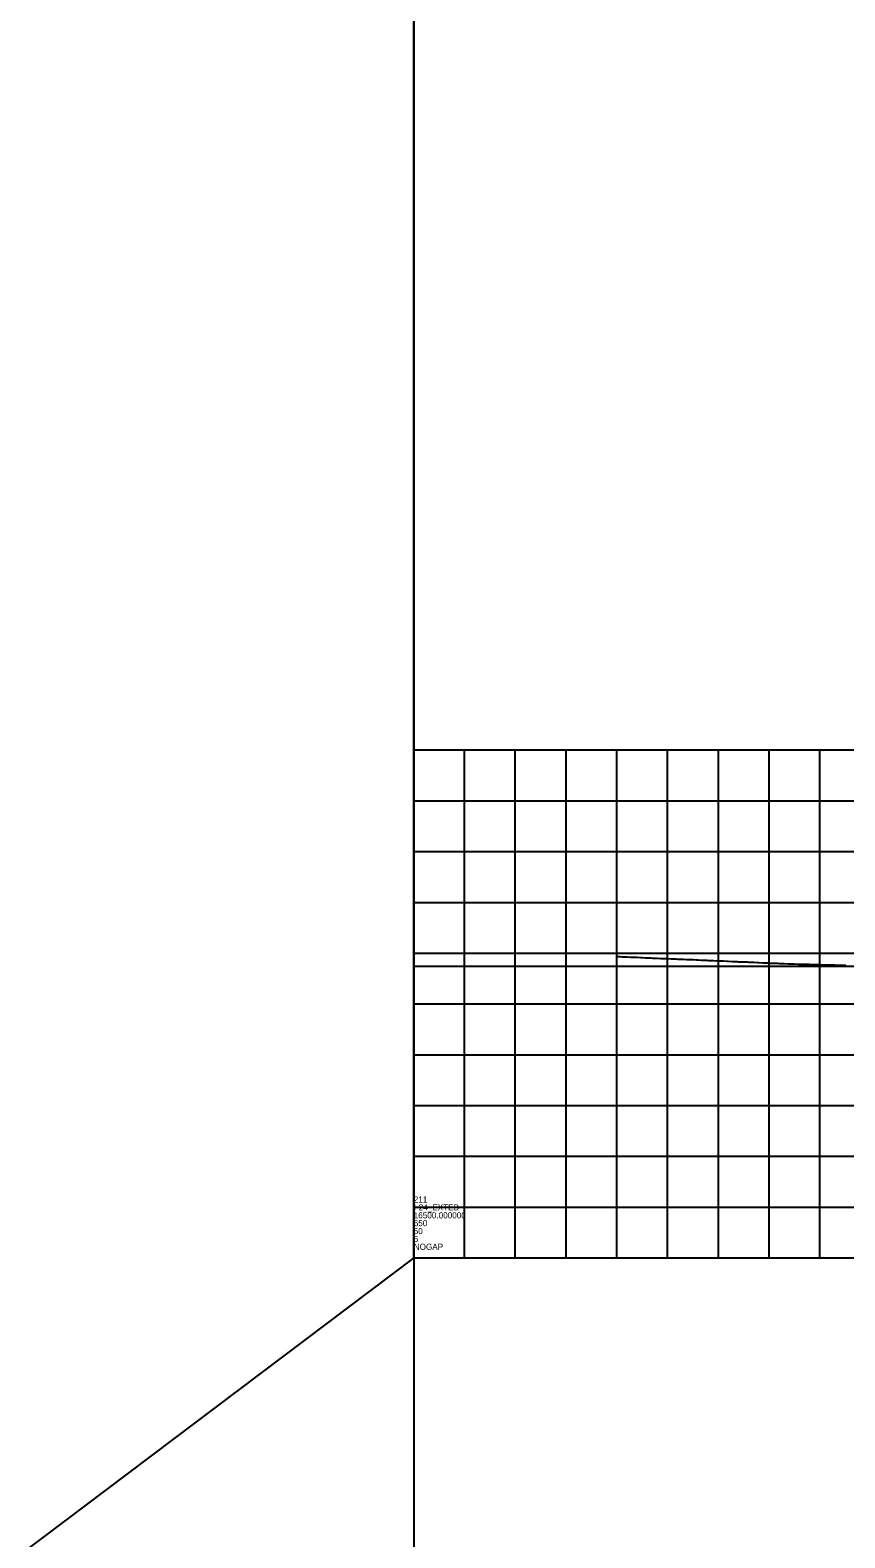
# Model space of a CAD drawing. Extents: x -7164 to 2214450, y -19642 to 253469.
# Drawn here: x -378 to 425, y -12276 to -10791 of the extents above; entities that cross this region are included whole.
import ezdxf

# ---------------------------------------------------------------- set-up
doc = ezdxf.new("R2010")
doc.units = 0
for name, color, linetype in [('DESIGN - SCRATCH - User 1', 7, 'Continuous'), ('DESIGN - SHEET - Light Grid', 7, 'Continuous'), ('SURVEY - PROFILE - Ground Line with Text', 7, 'Continuous'), ('XTREE', 7, 'Continuous')]:
    doc.layers.add(name, color=color, linetype=linetype)

msp = doc.modelspace()

# ---------------------------------------------------------------- linework, layer by layer
at = {"layer": 'DESIGN - SCRATCH - User 1'}
for p, q in [((1500, -11500), (0, -11500)), ((0, -11500), (0, -12000)), ((1500, -11500), (0, -11500)), ((0, -11500), (0, -12000)), ((0, -12000), (-6163.5, -16642.5)), ((0, -12000), (-6163.5, -16642.5)), ((0, -12000), (1500, -12000)), ((0, -12000), (1500, -12000))]:
    msp.add_line(p, q, dxfattribs=at)
at = {"layer": 'DESIGN - SHEET - Light Grid'}
for p, q in [((0, -9000), (0, -11500)), ((0, -9000), (0, -11500)), ((0, -12000), (0, -9500)), ((0, -12000), (0, -9500)), ((50, -12000), (50, -11500)), ((50, -12000), (50, -11500)), ((100, -12000), (100, -11500)), ((100, -12000), (100, -11500)), ((150, -12000), (150, -11500)), ((150, -12000), (150, -11500)), ((200, -12000), (200, -11500)), ((200, -12000), (200, -11500)), ((250, -12000), (250, -11500)), ((250, -12000), (250, -11500)), ((300, -12000), (300, -11500)), ((300, -12000), (300, -11500)), ((350, -12000), (350, -11500)), ((350, -12000), (350, -11500)), ((400, -12000), (400, -11500)), ((400, -12000), (400, -11500)), ((0, -11550), (1500, -11550)), ((0, -11550), (1500, -11550)), ((0, -11600), (1500, -11600)), ((0, -11600), (1500, -11600)), ((0, -11650), (1500, -11650)), ((0, -11650), (1500, -11650)), ((0, -11700), (1500, -11700)), ((0, -11700), (1500, -11700)), ((0, -11750), (1500, -11750)), ((0, -11750), (1500, -11750)), ((0, -11800), (1500, -11800)), ((0, -11800), (1500, -11800)), ((0, -11850), (1500, -11850)), ((0, -11850), (1500, -11850)), ((0, -11900), (1500, -11900)), ((0, -11900), (1500, -11900)), ((0, -11950), (1500, -11950)), ((0, -11950), (1500, -11950)), ((0, -12000), (1400, -12000)), ((0, -12000), (0, -14500)), ((0, -12000), (1400, -12000)), ((0, -12000), (0, -14500))]:
    msp.add_line(p, q, dxfattribs=at)
at = {"layer": 'SURVEY - PROFILE - Ground Line with Text'}
msp.add_lwpolyline([(200, -11703.2), (200.3, -11703.3), (203.4, -11703.4), (205.3, -11703.5), (208.4, -11703.6), (210.3, -11703.7), (213.4, -11703.8), (215.3, -11703.9), (218.4, -11704), (220.3, -11704.1), (223.4, -11704.2), (225.3, -11704.3), (228.4, -11704.5), (230.2, -11704.5), (233.4, -11704.7), (235.2, -11704.8), (238.4, -11704.9), (240.2, -11705), (243.5, -11705.1), (245.2, -11705.2), (248.5, -11705.3), (250.2, -11705.4), (253.5, -11705.5), (255.2, -11705.6), (258.5, -11705.7), (260.2, -11705.8), (263.5, -11705.9), (265.2, -11706), (268.5, -11706.1), (270.1, -11706.2), (273.5, -11706.4), (275.1, -11706.4), (278.5, -11706.6), (280.1, -11706.7), (283.5, -11706.8), (285.1, -11706.9), (288.6, -11707), (290.1, -11707.1), (293.6, -11707.2), (295.1, -11707.3), (298.6, -11707.4), (300.1, -11707.5), (303.6, -11707.7), (305.1, -11707.7), (308.6, -11707.9), (310, -11707.9), (313.6, -11708.1), (315, -11708.2), (318.6, -11708.3), (320, -11708.4), (323.6, -11708.5), (325, -11708.6), (328.6, -11708.7), (330, -11708.8), (333.7, -11709), (335, -11709), (338.7, -11709.2), (339.9, -11709.2), (343.7, -11709.4), (344.9, -11709.4), (348.7, -11709.6), (349.9, -11709.7), (353.7, -11709.8), (354.9, -11709.9), (358.7, -11710), (359.9, -11710.1), (363.7, -11710.2), (364.9, -11710.3), (368.7, -11710.4), (369.9, -11710.4), (373.8, -11710.6), (374.9, -11710.6), (378.8, -11710.7), (379.8, -11710.8), (383.8, -11710.9), (384.8, -11710.9), (388.8, -11711), (389.8, -11711), (393.8, -11711.1), (394.8, -11711.1), (398.8, -11711.2), (399.8, -11711.3), (403.8, -11711.4), (404.8, -11711.4), (408.8, -11711.5), (409.8, -11711.5), (413.8, -11711.6), (414.7, -11711.6), (418.9, -11711.7), (419.7, -11711.8), (421.4, -11711.8), (425.6, -11711.9)], dxfattribs=at)
msp.add_lwpolyline([(200, -11703.2), (200.3, -11703.3), (203.4, -11703.4), (205.3, -11703.5), (208.4, -11703.6), (210.3, -11703.7), (213.4, -11703.8), (215.3, -11703.9), (218.4, -11704), (220.3, -11704.1), (223.4, -11704.2), (225.3, -11704.3), (228.4, -11704.5), (230.2, -11704.5), (233.4, -11704.7), (235.2, -11704.8), (238.4, -11704.9), (240.2, -11705), (243.5, -11705.1), (245.2, -11705.2), (248.5, -11705.3), (250.2, -11705.4), (253.5, -11705.5), (255.2, -11705.6), (258.5, -11705.7), (260.2, -11705.8), (263.5, -11705.9), (265.2, -11706), (268.5, -11706.1), (270.1, -11706.2), (273.5, -11706.4), (275.1, -11706.4), (278.5, -11706.6), (280.1, -11706.7), (283.5, -11706.8), (285.1, -11706.9), (288.6, -11707), (290.1, -11707.1), (293.6, -11707.2), (295.1, -11707.3), (298.6, -11707.4), (300.1, -11707.5), (303.6, -11707.7), (305.1, -11707.7), (308.6, -11707.9), (310, -11707.9), (313.6, -11708.1), (315, -11708.2), (318.6, -11708.3), (320, -11708.4), (323.6, -11708.5), (325, -11708.6), (328.6, -11708.7), (330, -11708.8), (333.7, -11709), (335, -11709), (338.7, -11709.2), (339.9, -11709.2), (343.7, -11709.4), (344.9, -11709.4), (348.7, -11709.6), (349.9, -11709.7), (353.7, -11709.8), (354.9, -11709.9), (358.7, -11710), (359.9, -11710.1), (363.7, -11710.2), (364.9, -11710.3), (368.7, -11710.4), (369.9, -11710.4), (373.8, -11710.6), (374.9, -11710.6), (378.8, -11710.7), (379.8, -11710.8), (383.8, -11710.9), (384.8, -11710.9), (388.8, -11711), (389.8, -11711), (393.8, -11711.1), (394.8, -11711.1), (398.8, -11711.2), (399.8, -11711.3), (403.8, -11711.4), (404.8, -11711.4), (408.8, -11711.5), (409.8, -11711.5), (413.8, -11711.6), (414.7, -11711.6), (418.9, -11711.7), (419.7, -11711.8), (421.4, -11711.8), (425.6, -11711.9)], dxfattribs=at)
at = {"layer": 'XTREE'}
msp.add_line((0, -11712.8), (454.4, -11712.8), dxfattribs=at)
msp.add_line((0, -11712.8), (454.4, -11712.8), dxfattribs=at)
for points in [[(0, -12000), (1311.1, -12000), (1311.1, -11621.1)], [(0, -12000), (1311.1, -12000), (1311.1, -11621.1)], [(0, -12000), (454.4, -12000), (454.4, -11681.1)], [(0, -12000), (454.4, -12000), (454.4, -11681.1)]]:
    msp.add_lwpolyline(points, dxfattribs=at)

# ---------------------------------------------------------------- texts
at = {"layer": 'DESIGN - SHEET - Light Grid'}
for s, p in [('211', (0, -11945.6)), ('211', (0, -11945.6)), ('I-24_EXTEB', (0, -11953.4)), ('I-24_EXTEB', (0, -11953.4)), ('650', (0, -11968.9)), ('650', (0, -11968.9)), ('16500.000000', (0, -11961.2)), ('16500.000000', (0, -11961.2)), ('50', (0, -11976.7)), ('50', (0, -11976.7)), ('5', (0, -11984.5)), ('5', (0, -11984.5)), ('NOGAP', (0, -11992.2)), ('NOGAP', (0, -11992.2))]:
    msp.add_text(s, height=6, dxfattribs=at).set_placement(p)

doc.saveas('drawing.dxf')
